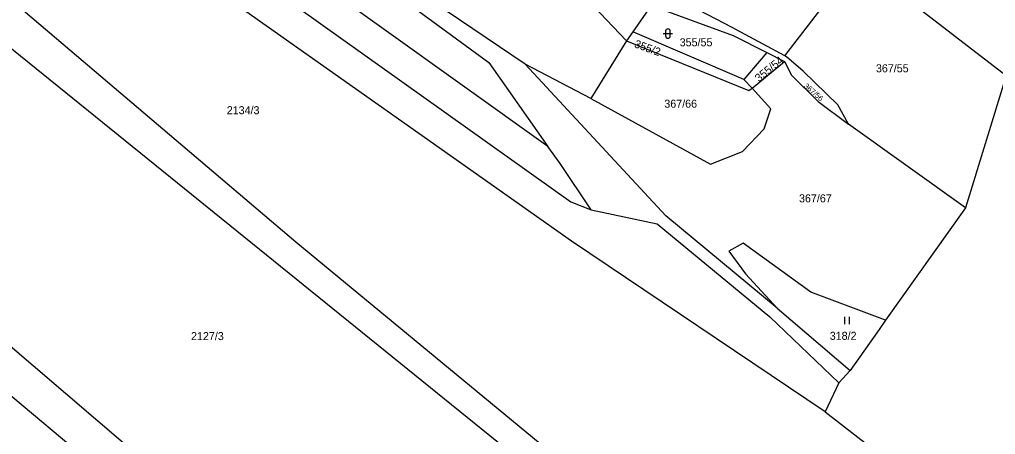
# Model space of a CAD drawing. Extents: x -679220 to -673243, y -1075091 to -1066557.
# Drawn here: x -675965.1 to -675757.8, y -1073009.1 to -1072921 of the extents above; entities that cross this region are included whole.
import ezdxf

# ---------------------------------------------------------------- set-up
doc = ezdxf.new("R2010")
doc.units = 0
for name, color, linetype in [('Hranice kat_území', 7, 'Continuous'), ('Hranice parcel', 7, 'Continuous'), ('Parcelní čísla', 7, 'Continuous'), ('Značky kultur', 7, 'Continuous')]:
    doc.layers.add(name, color=color, linetype=linetype)

msp = doc.modelspace()

# ---------------------------------------------------------------- linework, layer by layer
at = {"layer": 'Hranice kat_území'}
for p, q in [((-675755.51, -1072932.86), (-675764.17, -1072960.93)), ((-675764.17, -1072960.93), (-675781.11, -1072984.82)), ((-675788.67, -1072995.48), (-675791.05, -1072998.13)), ((-675791.05, -1072998.13), (-675793.98, -1073004.25))]:
    msp.add_line(p, q, dxfattribs=at)
for points in [[(-675781.11, -1072984.82), (-675782.5, -1072986.79), (-675788.67, -1072995.48)], [(-675793.98, -1073004.25), (-675753.27, -1073035.77), (-675718.19, -1073069.89)]]:
    msp.add_lwpolyline(points, dxfattribs=at)
at = {"layer": 'Hranice parcel'}
for p, q in [((-675802.54, -1072928.66), (-675787.01, -1072908.54)), ((-675787.01, -1072908.54), (-675755.51, -1072932.86)), ((-675830.9, -1072918), (-675834.79, -1072923.57)), ((-675834.79, -1072923.57), (-675836.14, -1072925.5)), ((-675811.22, -1072933.73), (-675834.79, -1072923.57)), ((-675836.14, -1072925.5), (-675843.72, -1072937.72)), ((-675806.37, -1072927.96), (-675811.22, -1072933.73)), ((-675806.37, -1072927.96), (-675802.56, -1072929.86)), ((-675843.72, -1072937.72), (-675857.72, -1072930.41)), ((-675809.49, -1072935.51), (-675802.56, -1072929.86)), ((-675809.49, -1072935.51), (-675811.22, -1072933.73)), ((-675764.17, -1072960.93), (-675789, -1072943.19)), ((-675804.15, -1072982.22), (-675788.67, -1072995.48))]:
    msp.add_line(p, q, dxfattribs=at)
for points in [[(-676362.1, -1072661.99), (-676336.64, -1072684.24), (-676216.32, -1072787.09), (-676115.3, -1072873.45), (-676044.35, -1072935.17), (-675981.55, -1072988.64), (-675892.7, -1073063.1), (-675794.84, -1073146.36)], [(-675852.87, -1072947.94), (-675923.92, -1072897.14), (-675952.34, -1072876.46), (-675990.88, -1072855.55), (-676033.92, -1072836.1), (-676058.2, -1072815.36), (-676065.61, -1072804.81)], [(-676065.61, -1072804.81), (-676057.1, -1072814.26), (-676037, -1072828.59), (-676029.23, -1072831.66), (-676001.87, -1072843.09), (-675975.54, -1072855.33), (-675948.8, -1072871.14), (-675884.19, -1072916.3), (-675865.43, -1072930.06), (-675852.87, -1072947.94)], [(-675793.98, -1073004.25), (-675847.84, -1072968.03), (-675970.96, -1072881.23), (-675995.4, -1072866.92), (-676015.48, -1072856.38), (-676040.93, -1072851.33)], [(-675748.91, -1073099.96), (-675833.86, -1073028.13), (-675906.4, -1072968.21), (-675995.92, -1072892.2), (-676032.53, -1072861.26), (-676040.93, -1072851.33)], [(-676002.17, -1072857.32), (-675993.29, -1072861.62), (-675956.13, -1072882.34), (-675927.65, -1072902.94), (-675848.02, -1072959.69), (-675843.66, -1072961.37)], [(-675798.03, -1073137.49), (-675762.6, -1073095.89), (-675838.52, -1073030.92), (-675991.71, -1072907.07), (-676049.8, -1072860.11), (-676083.67, -1072897.06), (-676041.03, -1072931.09), (-675976.07, -1072982.69), (-675886.17, -1073059.46), (-675798.03, -1073137.49)], [(-675857.72, -1072930.41), (-675882.54, -1072913.59), (-675917.21, -1072889.07)], [(-675836.14, -1072925.5), (-675844.57, -1072916.55), (-675862.06, -1072906.91), (-675867.49, -1072905.51), (-675872.58, -1072904.79), (-675887.07, -1072893.31)], [(-675830.9, -1072918), (-675813.53, -1072924.38), (-675806.37, -1072927.96)], [(-675802.54, -1072928.66), (-675813.69, -1072922.69), (-675822.25, -1072918.18)], [(-675836.14, -1072925.5), (-675810.15, -1072936.04), (-675809.49, -1072935.51)], [(-675804.15, -1072982.22), (-675827.81, -1072962.64), (-675857.72, -1072930.41)], [(-675802.56, -1072929.86), (-675801.13, -1072932.75), (-675795.47, -1072938.37), (-675789, -1072943.19)], [(-675789, -1072943.19), (-675791.27, -1072939.05), (-675798.61, -1072931.95), (-675802.15, -1072928.87), (-675802.54, -1072928.66)], [(-675843.72, -1072937.72), (-675818.29, -1072951.71), (-675811.54, -1072949.01), (-675806.89, -1072944.16), (-675805.52, -1072939.96), (-675809.49, -1072935.51)], [(-675843.66, -1072961.37), (-675850.25, -1072951.53), (-675852.87, -1072947.94)], [(-675843.66, -1072961.37), (-675829.66, -1072964.33), (-675805.74, -1072984.09), (-675791.05, -1072998.13)], [(-675781.11, -1072984.82), (-675796.97, -1072978.83), (-675811.37, -1072968.46), (-675814.42, -1072970.12), (-675810.87, -1072974.96), (-675804.15, -1072982.22)]]:
    msp.add_lwpolyline(points, dxfattribs=at)
at = {"layer": 'Značky kultur'}
for p, q in [((-675828.36, -1072923.95), (-675826.36, -1072923.95)), ((-675827.86, -1072923.45), (-675827.86, -1072924.45)), ((-675826.86, -1072924.45), (-675826.86, -1072923.45)), ((-675789.81, -1072985.62), (-675789.81, -1072984.12)), ((-675788.81, -1072985.62), (-675788.81, -1072984.12))]:
    msp.add_line(p, q, dxfattribs=at)
for centre, start, end in [((-675827.36, -1072923.45), 0, 180), ((-675827.36, -1072924.45), 180, 359.9879)]:
    msp.add_arc(centre, 0.5, start, end, dxfattribs=at)

# ---------------------------------------------------------------- texts
at = {"layer": 'Parcelní čísla'}
for s, height, rotation, p in [('355/2', 1.7, 340, (-675834.64, -1072926.81)), ('355/54', 1.7, 39, (-675808.03, -1072934.32)), ('367/56', 1.14, 319, (-675798.58, -1072935.24))]:
    msp.add_text(s, height=height, rotation=rotation, dxfattribs=at).set_placement(p)
for s, p in [('355/55', (-675824.86, -1072926.65)), ('367/55', (-675783.17, -1072932.17)), ('367/66', (-675828.13, -1072939.69)), ('2134/3', (-675921.1, -1072941.07)), ('367/67', (-675799.51, -1072959.78)), ('2127/3', (-675928.69, -1072989.03)), ('318/2', (-675792.98, -1072988.97))]:
    msp.add_text(s, height=1.7, dxfattribs=at).set_placement(p)

doc.saveas('drawing.dxf')
